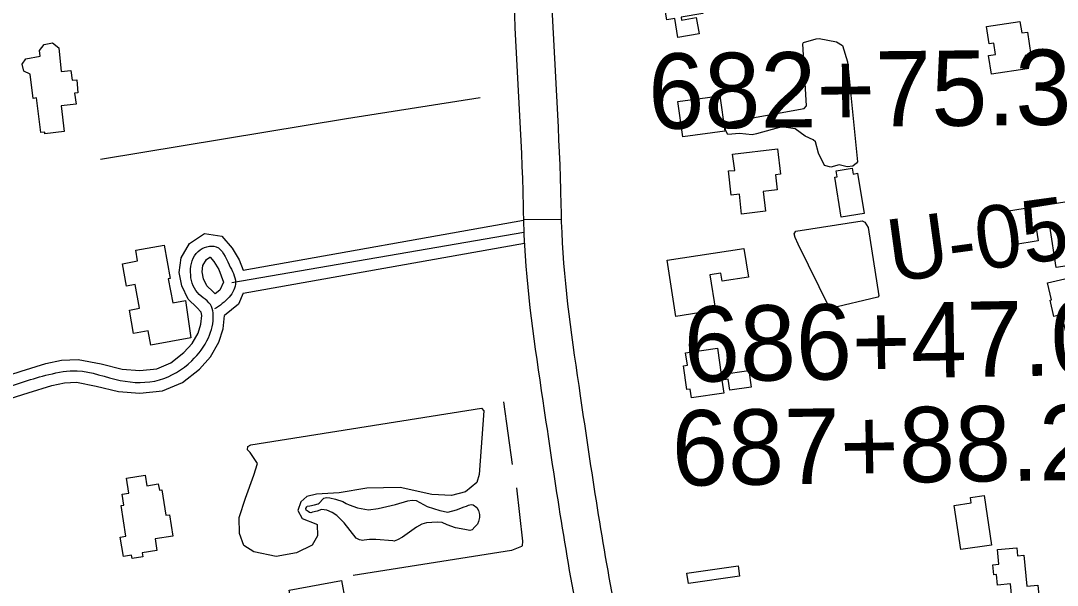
# Model space of a CAD drawing. Extents: x 3678539 to 3716648, y 451386 to 477139.
# Drawn here: x 3693361 to 3694736, y 459785 to 460535 of the extents above; entities that cross this region are included whole.
import ezdxf

# ---------------------------------------------------------------- set-up
doc = ezdxf.new("R2010")
doc.units = 0
for name, color, linetype in [('V-BLDG-OTLN', 7, 'Continuous'), ('V-RIVR-RANG-IDEN', 7, 'Continuous'), ('V-ROAD-CNTR', 7, 'Continuous'), ('V-SITE-VEGE', 7, 'Continuous'), ('V-SURV-IDEN', 7, 'Continuous'), ('V-TOPO-SHOR', 7, 'Continuous')]:
    doc.layers.add(name, color=color, linetype=linetype)

msp = doc.modelspace()

# ---------------------------------------------------------------- linework, layer by layer
at = {"layer": 'V-BLDG-OTLN'}
for points in [[(3694208.8, 460591.1), (3694251.8, 460598.5), (3694256.4, 460571.6), (3694261.1, 460572.4), (3694265.9, 460544.5), (3694237.1, 460539.6), (3694237.7, 460535.7), (3694257.3, 460539), (3694261, 460517.5), (3694232.9, 460512.7), (3694228.6, 460537.8), (3694218.3, 460536)], [(3694642.6, 460527.2), (3694686.8, 460533.8), (3694689.1, 460518.6), (3694696.9, 460519.8), (3694701.4, 460489.7), (3694693.7, 460488.5), (3694696.3, 460471), (3694648.9, 460463.9), (3694645.2, 460488.8), (3694654.3, 460490.1), (3694652, 460505.1), (3694646.1, 460504.2)], [(3693387.3, 460386.6), (3693381.6, 460432.3), (3693377.1, 460431.8), (3693373.1, 460464), (3693365, 460467.9), (3693362.7, 460477.2), (3693367.7, 460484.2), (3693386.6, 460487.9), (3693385.8, 460495.2), (3693392, 460503.4), (3693402.8, 460505.4), (3693411.4, 460498.9), (3693414.3, 460467.5), (3693427.1, 460468.7), (3693428.8, 460455.9), (3693435.4, 460456.4), (3693436.7, 460438.9), (3693432.2, 460438.5), (3693434.4, 460424.1), (3693414.6, 460421.7), (3693418.4, 460387.9), (3693392.9, 460384.8), (3693392.6, 460386.8)], [(3694239.4, 460380.5), (3694232.8, 460427.4), (3694288.5, 460435.3), (3694295.1, 460388.4)], [(3694305.1, 460357.7), (3694365, 460364.8), (3694368.9, 460331.1), (3694362.2, 460330.3), (3694364.5, 460310.5), (3694346, 460308.3), (3694349.1, 460281.9), (3694317.4, 460278.2), (3694314.4, 460304.4), (3694303.7, 460303.1), (3694300, 460335.5), (3694308.4, 460336)], [(3694471.4, 460332.3), (3694480.1, 460279.1), (3694449.6, 460274.1), (3694441, 460327.2), (3694444.2, 460327.7), (3694442.9, 460335.6), (3694464.3, 460339.1), (3694465.5, 460331.3)], [(3694671.5, 460282.7), (3694768.5, 460297.9), (3694774.8, 460257.3), (3694795.3, 460260.5), (3694802, 460217.6), (3694735, 460207.1), (3694726.3, 460262.2), (3694708.3, 460259.4), (3694711, 460242.6), (3694678.5, 460237.5)], [(3693586.6, 460114), (3693533.2, 460104.3), (3693529.8, 460123.1), (3693510.6, 460119.6), (3693504.9, 460150.6), (3693518.4, 460153.1), (3693512.6, 460184.6), (3693501.1, 460182.5), (3693495.7, 460212.2), (3693515.9, 460215.9), (3693513.3, 460230.1), (3693551, 460237), (3693559.2, 460192.5), (3693556.6, 460192.1), (3693562.5, 460160.2), (3693579.4, 460163.3)], [(3694230.3, 460142.4), (3694218.8, 460217), (3694320.5, 460232.7), (3694326.5, 460194.3), (3694291.5, 460188.9), (3694289.8, 460199.7), (3694275.4, 460197.4), (3694282.7, 460150.5)], [(3694789.7, 460124), (3694749.1, 460116.2), (3694742.5, 460144.8), (3694731.9, 460142.3), (3694726.8, 460164), (3694728.5, 460164.4), (3694723.2, 460186.9), (3694757.9, 460195), (3694763.2, 460172.4), (3694780.7, 460174.1)], [(3694293.7, 460040.6), (3694250.7, 460034.4), (3694249.1, 460045.8), (3694244.9, 460045.2), (3694240.4, 460076.9), (3694245.4, 460077.6), (3694243.1, 460093.9), (3694285.4, 460100), (3694290.4, 460065.3), (3694326.8, 460070.5), (3694330, 460048.5), (3694301.6, 460044.4), (3694299.5, 460059.1), (3694291.2, 460057.9)], [(3693496.9, 459823.8), (3693492.8, 459849.3), (3693500.3, 459850.5), (3693493.8, 459891.3), (3693497.6, 459891.9), (3693495.2, 459906.5), (3693504, 459907.9), (3693500.9, 459927.5), (3693525.8, 459931.5), (3693528, 459917.5), (3693543.3, 459920), (3693544.7, 459911.5), (3693548.1, 459912), (3693553.5, 459878.3), (3693558.1, 459879.1), (3693562.7, 459850.7), (3693539, 459846.9), (3693541.4, 459831.8), (3693521.9, 459828.7), (3693522.8, 459823.3), (3693508.6, 459821), (3693507.8, 459825.6)], [(3694639.2, 459904.7), (3694649.1, 459838.9), (3694608.4, 459832.8), (3694599.6, 459891.3), (3694622.2, 459894.7), (3694621.1, 459902)], [(3694713.2, 459758), (3694677.3, 459754.6), (3694674.2, 459787.3), (3694657, 459785.7), (3694655.7, 459799.6), (3694652.3, 459799.2), (3694651, 459812.7), (3694658.8, 459813.5), (3694656.9, 459832.8), (3694682.6, 459835.2), (3694683.6, 459824.5), (3694691.9, 459825.3), (3694695.8, 459784.4), (3694710.5, 459785.8)], [(3694314.6, 459797.6), (3694246.8, 459787.7), (3694244.8, 459801.4), (3694312.7, 459811.3)], [(3693779.8, 459723.1), (3693729.1, 459713.7), (3693717, 459779), (3693786.2, 459791.8), (3693791.1, 459765.3), (3693773.6, 459761.6)]]:
    msp.add_lwpolyline(points, close=True, dxfattribs=at)
at = {"layer": 'V-ROAD-CNTR'}
for points in [[(3693655.9, 460203.8), (3694027.9, 460270.3)], [(3694027.9, 460271.1), (3694078, 460271.4)], [(3693329.5, 460059.5), (3693361.5, 460069.5), (3693394.2, 460079.7), (3693414.7, 460084.1), (3693436.8, 460085.3), (3693467.6, 460079.2), (3693495.3, 460072.2), (3693518.6, 460070.5), (3693541.2, 460072.8), (3693559.8, 460080.6), (3693577.3, 460094.4), (3693588.2, 460106.5), (3693596, 460120.2), (3693599.8, 460132.2), (3693601, 460143.4), (3693600.1, 460148.1), (3693594.3, 460154.2), (3693582.8, 460165.1), (3693574.6, 460182.8), (3693570.8, 460200.8), (3693573.8, 460220), (3693584.9, 460239.2), (3693604.7, 460252.2), (3693627.7, 460248.8), (3693641.4, 460232.8), (3693650.8, 460217.5), (3693655.9, 460203.8)], [(3694028.4, 460253.9), (3693640.7, 460186.7)], [(3693655.9, 460173), (3694029.2, 460239.5)], [(3693618.6, 460172.1), (3693615.5, 460175.4), (3693607.7, 460182.8), (3693603.3, 460192.3), (3693601.3, 460201.7), (3693602.6, 460209.9), (3693607.3, 460218), (3693611.6, 460220.8), (3693612.2, 460220.8), (3693617.1, 460215.1), (3693623.6, 460204.4), (3693629.7, 460188), (3693625.1, 460177.3), (3693618.6, 460172.1)], [(3693655.9, 460173), (3693649.7, 460158.7), (3693631.3, 460143.7)], [(3693338.5, 460030.9), (3693370.5, 460040.9), (3693401.8, 460050.6), (3693418.7, 460054.3), (3693434.7, 460055.1), (3693461, 460049.9), (3693490.4, 460042.5), (3693519, 460040.4), (3693548.7, 460043.4), (3693575.2, 460054.6), (3693597.9, 460072.4), (3693612.6, 460088.8), (3693623.7, 460108.1), (3693629.3, 460126), (3693631.3, 460143.7)]]:
    msp.add_lwpolyline(points, dxfattribs=at)
for points in [[(3694092.6, 461108.8), (3694067.8, 460806.3), (3694064.9, 460576.3), (3694077.1, 460310.3), (3694078.6, 460253.8), (3694103.2, 460036.9), (3694151.9, 459740.3), (3694195, 459550.1), (3694267, 459267.3)], [(3694032.5, 461094.4), (3694017.7, 460807.8), (3694014.8, 460575.4), (3694027, 460308.5), (3694028.6, 460250.3), (3694053.6, 460030.1), (3694102.7, 459730.7), (3694146.3, 459538.4), (3694218.5, 459254.9)], [(3694788, 460664.6), (3694854.8, 460447.7), (3694908.2, 460241.9), (3694923.9, 460065.9), (3694912.9, 459920.9), (3694867.4, 459717.8), (3694810.9, 459555), (3694731.9, 459268.4), (3694721.4, 459066.6), (3694739.2, 458851.9), (3694832.3, 458599.2), (3694993.1, 458299.7)], [(3693334, 460045.2), (3693398, 460065.2), (3693435.7, 460070.2), (3693492.8, 460057.4), (3693544.9, 460058.1), (3693587.6, 460083.4), (3693609.9, 460114.1), (3693616.2, 460144.1), (3693614, 460155.3), (3693595.3, 460174), (3693586.1, 460201.2), (3693596.1, 460228.6), (3693620, 460234.8), (3693637.2, 460210.9), (3693645.8, 460187.6), (3693637.4, 460168), (3693617.9, 460152.2)]]:
    msp.add_spline(points, degree=3, dxfattribs=at)
at = {"layer": 'V-SITE-VEGE'}
for points in [[(3694297.9, 460399.8), (3694400.2, 460418.2), (3694403.7, 460421.8), (3694398.5, 460504), (3694399.6, 460505.8), (3694416.2, 460510.6), (3694420.3, 460511.3), (3694443.4, 460506.7), (3694451.1, 460502), (3694457.8, 460480.1), (3694471.1, 460347.7), (3694469.9, 460345.9), (3694465.2, 460341.7), (3694457.5, 460341.1), (3694446.8, 460343.4), (3694435.6, 460340.3), (3694427.3, 460342.7), (3694419.5, 460359.2), (3694415.3, 460373.9), (3694412.3, 460376.9), (3694401.6, 460381.5), (3694388.5, 460391.5), (3694370.8, 460393.8), (3694337.1, 460384.7), (3694331.2, 460383.5), (3694314.6, 460385.1), (3694299.2, 460383.8), (3694296.2, 460389.7), (3694296.8, 460401)], [(3694389.4, 460255.4), (3694477.5, 460269), (3694481.1, 460267.3), (3694485.3, 460260.2), (3694499.5, 460169.7), (3694498.3, 460168), (3694435.1, 460152.8), (3694433.9, 460153.9), (3694392.5, 460238.3), (3694388.3, 460247.1), (3694387.1, 460251.9)], [(3693666.3, 459971.9), (3693972, 460020.7), (3693975.5, 460017.1), (3693969, 459932.5), (3693966.1, 459921.8), (3693950.8, 459909.3), (3693932.5, 459904.4), (3693906.4, 459906), (3693864.4, 459915.2), (3693820, 459914.3), (3693783.3, 459908.2), (3693753.2, 459906.2), (3693740.2, 459903.2), (3693732.5, 459896), (3693728.5, 459884.7), (3693734.4, 459874.1), (3693752.2, 459867.1), (3693754, 459866), (3693754.7, 459851.2), (3693747.7, 459838.7), (3693726.5, 459828.5), (3693699.9, 459823.6), (3693670.2, 459829.9), (3693656.6, 459838.1), (3693651.1, 459854), (3693650.4, 459875.3), (3693659.1, 459900.9), (3693670.2, 459931.7), (3693674.8, 459947.1), (3693665.2, 459961.8), (3693661.6, 459965.4), (3693662.2, 459969.5)]]:
    msp.add_lwpolyline(points, close=True, dxfattribs=at)
at = {"layer": 'V-TOPO-SHOR'}
msp.add_line((3694001.3, 460029.1), (3694012.8, 459945.7), dxfattribs=at)
for points in [[(3693970.5, 460432.3), (3693793.2, 460404.6), (3693466.8, 460350.6)], [(3694018.8, 459914.6), (3694026.8, 459843.8), (3694026.2, 459838), (3694025.1, 459836.8), (3694011.9, 459831.6), (3693801.7, 459798.5)], [(3693854.4, 459844.6), (3693832, 459846.4), (3693823.4, 459846.4), (3693816.7, 459845.2), (3693814.7, 459845.1), (3693810.4, 459845.9), (3693805.7, 459848.2), (3693789.8, 459868.2), (3693780.3, 459877.9), (3693774, 459882.2), (3693766.9, 459885.3), (3693759.8, 459886.1), (3693754, 459884), (3693748.1, 459882.4), (3693745.7, 459881.6), (3693743.8, 459882), (3693742.2, 459883.2), (3693739.4, 459885.1), (3693739, 459887.5), (3693740.2, 459889.5), (3693741, 459890.3), (3693744.5, 459891.1), (3693750.4, 459892.3), (3693755.5, 459893.5), (3693756.6, 459894.3), (3693762.1, 459900.2), (3693762.9, 459901), (3693766.4, 459901.8), (3693771.1, 459901.5), (3693778.6, 459899.9), (3693788.1, 459896.5), (3693792.4, 459894.1), (3693796.7, 459892.2), (3693807.8, 459888.3), (3693822.3, 459885.7), (3693834.9, 459887.3), (3693858.1, 459892.6), (3693874.5, 459897.4), (3693880, 459898.2), (3693885.5, 459897.9), (3693900.1, 459890.1), (3693916.7, 459884.7), (3693927.7, 459882.4), (3693939.1, 459885.6), (3693949.3, 459889.6), (3693952.4, 459890.5), (3693955.1, 459891.6), (3693958.3, 459892.5), (3693961, 459892.1), (3693965.8, 459888.6), (3693968.1, 459884.7), (3693969.4, 459879.2), (3693969.4, 459875.2), (3693968.2, 459870.1), (3693967.1, 459866.6), (3693963.2, 459863), (3693959.7, 459859.1), (3693956.9, 459858.3), (3693950.2, 459859.4), (3693937.6, 459861.7), (3693926.6, 459865.5), (3693919.9, 459868.6), (3693913.2, 459869.4), (3693899.1, 459868.5), (3693893.2, 459866.5), (3693885.8, 459862.5), (3693867.4, 459849.4), (3693860.7, 459845.8), (3693856.4, 459844.2), (3693854.4, 459844.6)]]:
    msp.add_lwpolyline(points, dxfattribs=at)

# ---------------------------------------------------------------- texts
at = {"layer": 'V-RIVR-RANG-IDEN'}
msp.add_text('U-050', height=83, rotation=7.7613, dxfattribs=at).set_placement((3694516.7, 460187.6))
at = {"layer": 'V-SURV-IDEN'}
for s, rotation, p in [('682+75.3', 0.5794, (3694193.9, 460391.2)), ('686+47.0', 1.0081, (3694241.4, 460055.2)), ('687+88.2', 0.8247, (3694225.5, 459917.4))]:
    msp.add_text(s, height=100, rotation=rotation, dxfattribs=at).set_placement(p)

doc.saveas('drawing.dxf')
